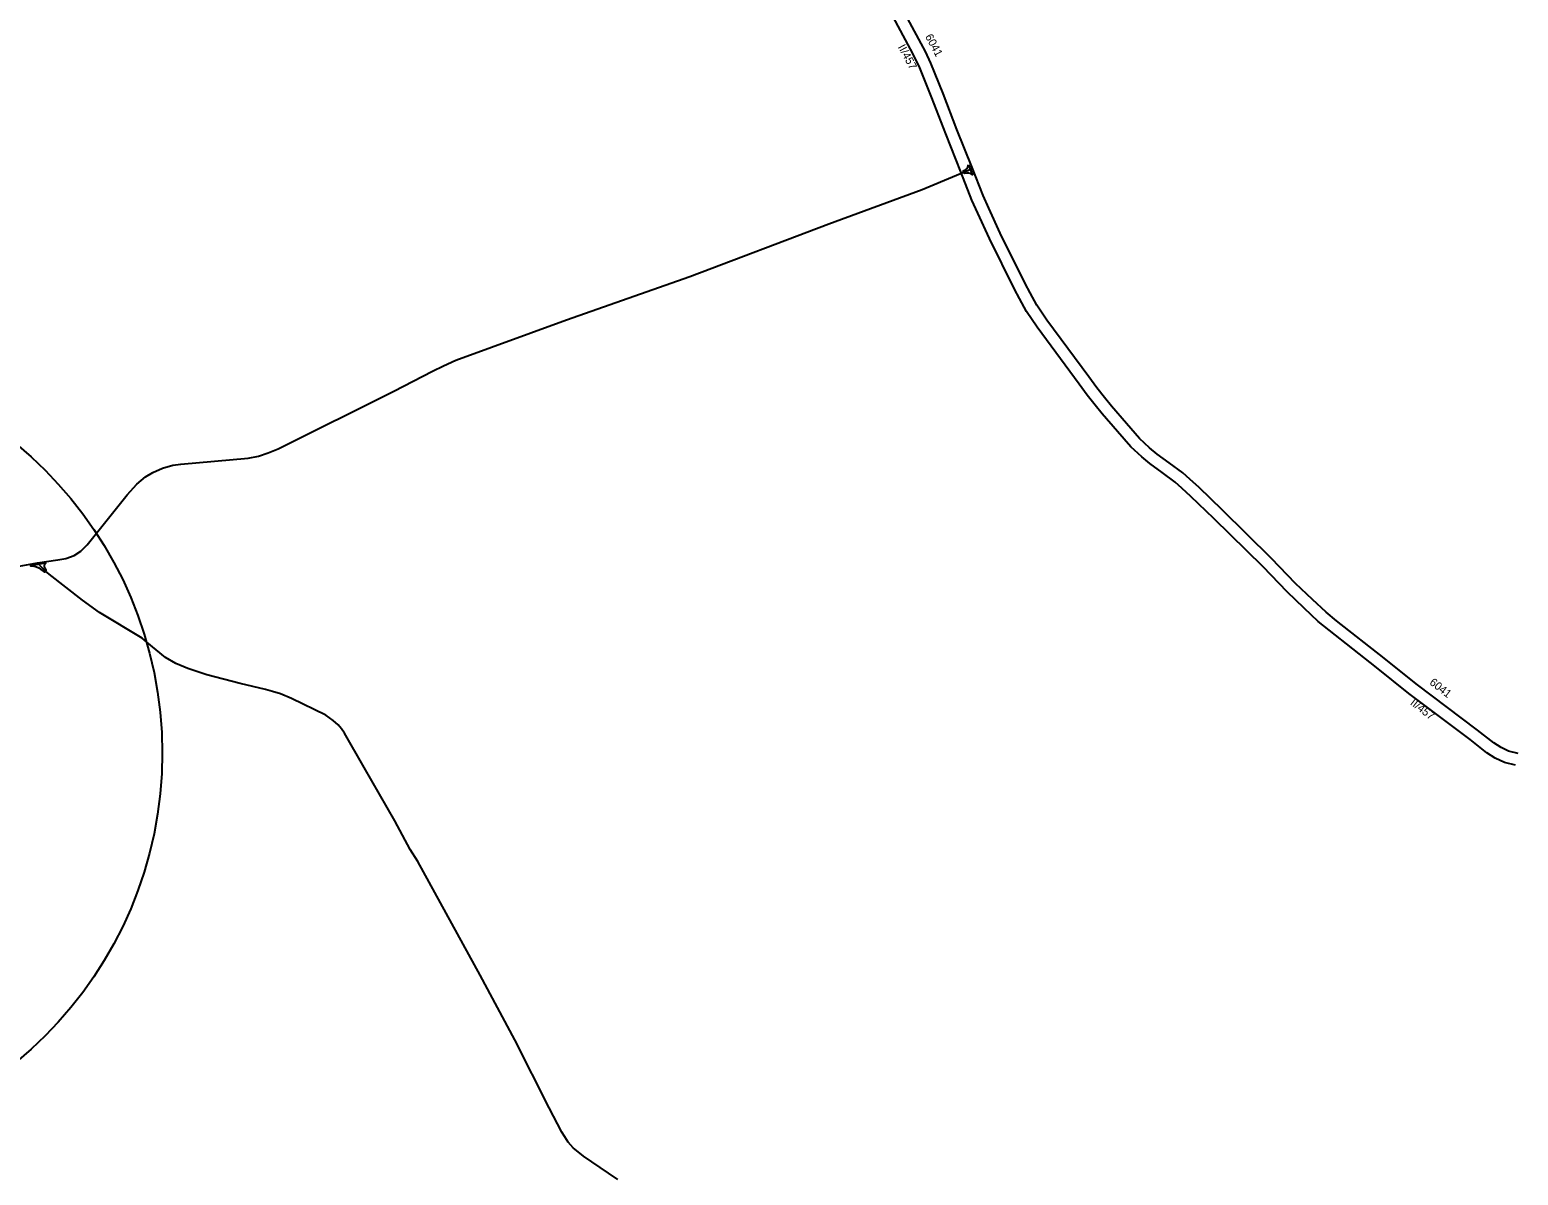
# Model space of a CAD drawing. Extents: x -546703 to -534152, y -1046534 to -1035676.
# Drawn here: x -542103 to -540243, y -1039091 to -1037660 of the extents above; entities that cross this region are included whole.
import ezdxf

# ---------------------------------------------------------------- set-up
doc = ezdxf.new("R2010")
doc.units = 0
for name, color, linetype in [('Vrstva 11', 7, 'Continuous'), ('Vrstva 17', 7, 'Continuous'), ('Vrstva 22', 7, 'Continuous'), ('Vrstva 26', 7, 'Continuous'), ('Vrstva 3', 7, 'Continuous'), ('Vrstva 7', 7, 'Continuous')]:
    doc.layers.add(name, color=color, linetype=linetype)

msp = doc.modelspace()

# ---------------------------------------------------------------- linework, layer by layer
at = {"layer": 'Vrstva 11'}
msp.add_lwpolyline([(-542083, -1038325.6), (-542093.3, -1038327.7), (-542102.5, -1038329.5), (-542098.3, -1038329.8), (-542095.2, -1038330.5), (-542092.2, -1038331.9), (-542089.5, -1038333.9), (-542085.2, -1038337.3), (-542082.8, -1038334.7), (-542084.7, -1038332.3), (-542085.2, -1038330.4), (-542085.2, -1038328.6), (-542084.4, -1038327)], close=True, dxfattribs=at)
msp.add_lwpolyline([(-541368.4, -1039096.4), (-541380.3, -1039088.3), (-541411.3, -1039067.1), (-541424.4, -1039056.6), (-541430.5, -1039049.6), (-541434.8, -1039043.1), (-541438.6, -1039037), (-541454.5, -1039006.8), (-541497.1, -1038921.7), (-541540.6, -1038841), (-541618.5, -1038698.9), (-541627.9, -1038684.1), (-541647.1, -1038648.2), (-541685.5, -1038581.4), (-541710, -1038538.5), (-541713.8, -1038533.1), (-541717.9, -1038528.1), (-541724.1, -1038522.6), (-541733.3, -1038516), (-541776.3, -1038495.2), (-541790.2, -1038489.5), (-541800.1, -1038486.3), (-541808.8, -1038483.8), (-541840.7, -1038476.4), (-541882.2, -1038465.5), (-541905.8, -1038457.9), (-541920.8, -1038451.3), (-541933.8, -1038444), (-541957.2, -1038424.6), (-541963, -1038420), (-542016.5, -1038387.8), (-542037.7, -1038372.5), (-542079.3, -1038340), (-542084, -1038336), (-542087.7, -1038332.3), (-542093.6, -1038325.7)], dxfattribs=at)
at = {"layer": 'Vrstva 17'}
msp.add_lwpolyline([(-540246.7, -1038578.6), (-540260.3, -1038575.3), (-540272, -1038569.8), (-540282.5, -1038563), (-540303.2, -1038546.5), (-540380, -1038488.9), (-540420.2, -1038456.3), (-540479.6, -1038409.9), (-540493.3, -1038398.8), (-540510.6, -1038382.4), (-540532, -1038362), (-540562, -1038330.8), (-540623.5, -1038270.1), (-540652.2, -1038242.6), (-540663.6, -1038232.2), (-540672, -1038224.8), (-540688.3, -1038212.6), (-540703.5, -1038201.6), (-540713.7, -1038193.3), (-540727.2, -1038180.6), (-540744.2, -1038161.6), (-540763.2, -1038139.4), (-540771.9, -1038128.5), (-540781.9, -1038116), (-540791.9, -1038102.3), (-540844.5, -1038031), (-540857.8, -1038011.6), (-540866.5, -1037995.3), (-540872.9, -1037983.6), (-540904, -1037920.2), (-540918.6, -1037888.7), (-540925.9, -1037872.3), (-540939.8, -1037837.2), (-540958.7, -1037789.7), (-540976.1, -1037744.7), (-540991.2, -1037707), (-540997.6, -1037693.3), (-541002.6, -1037683.9), (-541030.6, -1037631.8)], dxfattribs=at)
at = {"layer": 'Vrstva 22'}
msp.add_lwpolyline([(-540243.2, -1038564), (-540255.3, -1038561.1), (-540264.7, -1038556.6), (-540273.7, -1038550.8), (-540294.1, -1038534.6), (-540370.8, -1038477), (-540410.9, -1038444.6), (-540470.3, -1038398.2), (-540483.4, -1038387.5), (-540500.3, -1038371.6), (-540521.4, -1038351.4), (-540551.4, -1038320.2), (-540613.1, -1038259.4), (-540642, -1038231.6), (-540653.5, -1038221.1), (-540662.5, -1038213.1), (-540679.4, -1038200.5), (-540694.4, -1038189.7), (-540703.9, -1038182.1), (-540716.4, -1038170.1), (-540732.9, -1038151.7), (-540751.6, -1038129.9), (-540760.2, -1038119.1), (-540770, -1038106.9), (-540779.8, -1038093.4), (-540832.2, -1038022.3), (-540845, -1038003.8), (-540853.3, -1037988.2), (-540859.6, -1037976.7), (-540890.5, -1037913.7), (-540904.9, -1037882.5), (-540912, -1037866.5), (-540925.8, -1037831.7), (-540944.7, -1037784.2), (-540962.1, -1037739.2), (-540977.4, -1037701.1), (-540984.1, -1037686.6), (-540989.3, -1037676.8), (-541017.6, -1037624.3)], dxfattribs=at)
at = {"layer": 'Vrstva 26'}
msp.add_circle((-542437.9, -1038563.4), 500, dxfattribs=at)
at = {"layer": 'Vrstva 3'}
msp.add_lwpolyline([(-540243.2, -1038564), (-540255.3, -1038561.1), (-540264.7, -1038556.6), (-540273.7, -1038550.8), (-540294.1, -1038534.6), (-540370.8, -1038477), (-540410.9, -1038444.6), (-540470.3, -1038398.2), (-540483.4, -1038387.5), (-540500.3, -1038371.6), (-540521.4, -1038351.4), (-540551.4, -1038320.2), (-540613.1, -1038259.4), (-540642, -1038231.6), (-540653.5, -1038221.1), (-540662.5, -1038213.1), (-540679.4, -1038200.5), (-540694.4, -1038189.7), (-540703.9, -1038182.1), (-540716.4, -1038170.1), (-540732.9, -1038151.7), (-540751.6, -1038129.9), (-540760.2, -1038119.1), (-540770, -1038106.9), (-540779.8, -1038093.4), (-540832.2, -1038022.3), (-540845, -1038003.8), (-540853.3, -1037988.2), (-540859.6, -1037976.7), (-540890.5, -1037913.7), (-540904.9, -1037882.5), (-540912, -1037866.5), (-540925.8, -1037831.7), (-540944.7, -1037784.2), (-540962.1, -1037739.2), (-540977.4, -1037701.1), (-540984.1, -1037686.6), (-540989.3, -1037676.8), (-541017.6, -1037624.3)], dxfattribs=at)
at = {"layer": 'Vrstva 7'}
msp.add_lwpolyline([(-542176.8, -1038340.7), (-542093.6, -1038325.7), (-542068.2, -1038321.9), (-542058.2, -1038320.1), (-542048.1, -1038316.4), (-542039.5, -1038311.2), (-542031.6, -1038303.3), (-541981.7, -1038240.5), (-541969.7, -1038227.2), (-541959, -1038218.2), (-541949.8, -1038212.6), (-541937.7, -1038207.4), (-541924.7, -1038203.8), (-541914.8, -1038202.4), (-541830.7, -1038194.7), (-541817.4, -1038192.3), (-541805.5, -1038188.3), (-541793.1, -1038183.2), (-541648.5, -1038111), (-541600, -1038086), (-541586.2, -1038079.3), (-541570.9, -1038072.4), (-541432.8, -1038022.1), (-541278.5, -1037967.8), (-541104.7, -1037902), (-540988.1, -1037859.1), (-540945.1, -1037841.3), (-540925.3, -1037832.9)], dxfattribs=at)
msp.add_lwpolyline([(-540930.4, -1037828.3), (-540928.6, -1037832.8), (-540925.4, -1037840.9), (-540927.6, -1037839.1), (-540929.8, -1037838.6), (-540931.9, -1037838.5), (-540934.8, -1037839.1), (-540936.8, -1037835.6), (-540934, -1037834.4), (-540932.1, -1037832.7), (-540931, -1037831)], close=True, dxfattribs=at)

# ---------------------------------------------------------------- texts
at = {"layer": 'Vrstva 22'}
for rotation, p in [(298.4321, (-540984.8, -1037668)), (322.0509, (-540354.9, -1038476.7))]:
    msp.add_text('6041', height=10, rotation=rotation, dxfattribs=at).set_placement(p)
at = {"layer": 'Vrstva 3'}
for rotation, p in [(298.4321, (-541018.8, -1037681)), (322.0509, (-540379, -1038502.1))]:
    msp.add_text('II/457', height=10, rotation=rotation, dxfattribs=at).set_placement(p)

doc.saveas('drawing.dxf')
